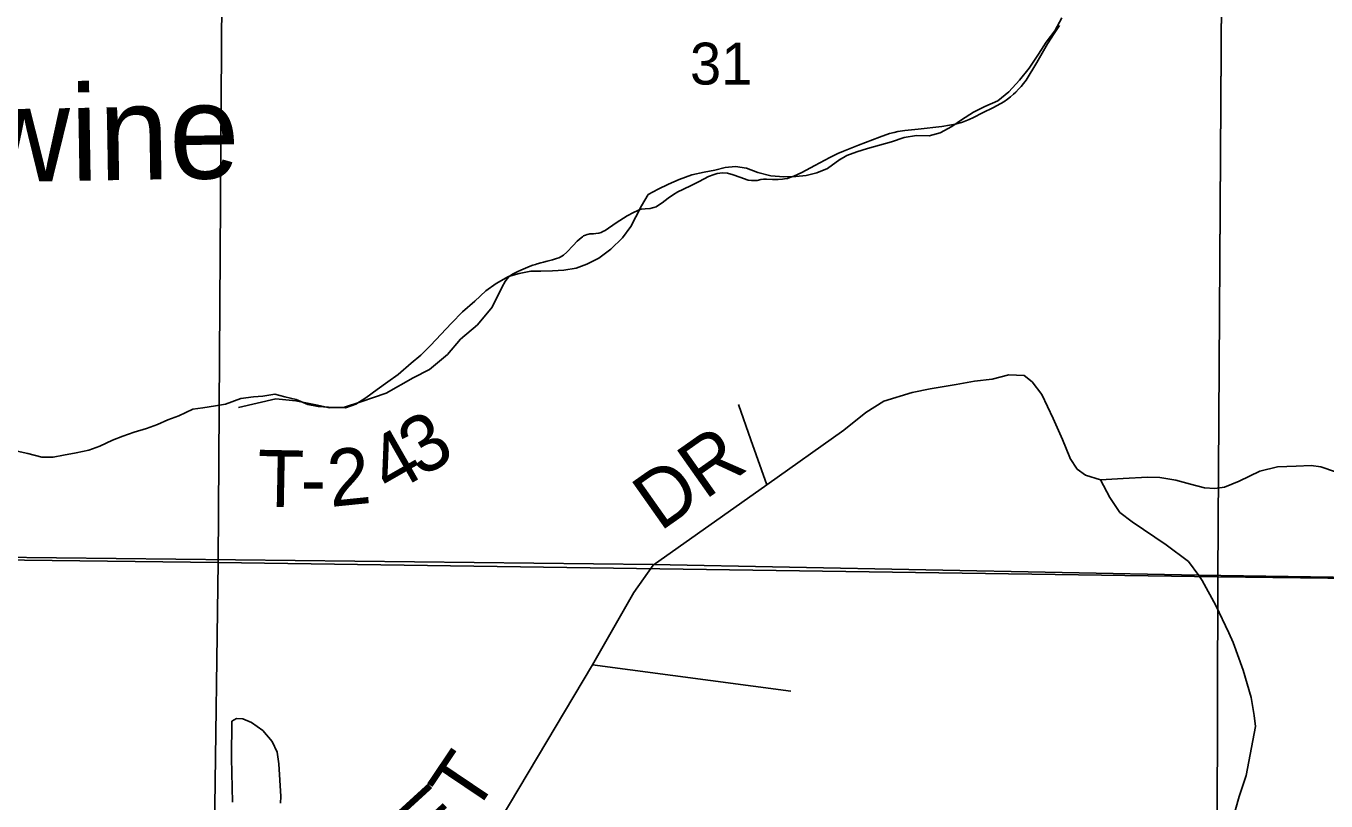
# Model space of a CAD drawing. Extents: x 0 to 34, y 0 to 22.
# Drawn here: x 6.268 to 7.567, y 18.884 to 19.658 of the extents above; entities that cross this region are included whole.
import ezdxf

# ---------------------------------------------------------------- set-up
doc = ezdxf.new("R2010")
doc.units = 0
for name, color, linetype in [('Default', 7, 'Continuous'), ('GM_X_County_Road', 7, 'Continuous'), ('GM_X_County_Road_Text', 7, 'Continuous'), ('GM_X_Minor_River', 7, 'Continuous'), ('GM_X_Minor_River_Text', 7, 'Continuous'), ('GM_X_Section', 7, 'Continuous'), ('GM_X_Section_Text', 7, 'Continuous'), ('GM_X_Township_Road', 7, 'Continuous'), ('GM_X_Township_Road_Text', 7, 'Continuous')]:
    doc.layers.add(name, color=color, linetype=linetype)

msp = doc.modelspace()

# ---------------------------------------------------------------- linework, layer by layer
at = {"layer": 'Default'}
for p, q in [((6.8944, 19.1204), (5.4005, 19.1369)), ((5.4005, 19.1369), (6.8944, 19.1204)), ((7.4393, 19.1097), (6.8944, 19.1204)), ((6.8944, 19.1204), (7.4393, 19.1097)), ((7.7845, 19.1045), (7.4393, 19.1097)), ((7.4393, 19.1097), (7.7845, 19.1045))]:
    msp.add_line(p, q, dxfattribs=at)
at = {"layer": 'GM_X_County_Road'}
for p, q in [((7.1711, 19.2958), (7.1971, 19.3001)), ((7.1971, 19.3001), (7.2154, 19.3036)), ((7.2154, 19.3036), (7.2333, 19.3055)), ((7.2333, 19.3055), (7.25, 19.3098)), ((7.25, 19.3098), (7.2652, 19.309)), ((7.2652, 19.309), (7.273, 19.3028)), ((7.273, 19.3028), (7.2827, 19.29)), ((7.1248, 19.2834), (7.1532, 19.2923)), ((7.1532, 19.2923), (7.1711, 19.2958)), ((7.2827, 19.29), (7.2943, 19.2663)), ((7.1069, 19.2721), (7.1248, 19.2834)), ((7.0851, 19.2546), (7.1069, 19.2721)), ((7.2943, 19.2663), (7.3033, 19.2453)), ((7.0081, 19.1998), (7.0851, 19.2546)), ((7.3033, 19.2453), (7.3107, 19.2272)), ((7.3107, 19.2272), (7.3111, 19.2262)), ((7.3111, 19.2262), (7.3181, 19.2157)), ((7.3181, 19.2157), (7.3265, 19.2094)), ((7.3265, 19.2094), (7.3414, 19.2048)), ((7.4798, 19.2037), (7.5006, 19.2136)), ((7.5006, 19.2136), (7.5183, 19.2179)), ((7.5183, 19.2179), (7.5368, 19.2186)), ((7.5368, 19.2186), (7.5518, 19.2192)), ((7.5518, 19.2192), (7.5615, 19.2179)), ((7.5615, 19.2179), (7.5761, 19.213)), ((6.8946, 19.1198), (7.0081, 19.1998)), ((7.3414, 19.2048), (7.364, 19.2062)), ((7.364, 19.2062), (7.3883, 19.2077)), ((7.3883, 19.2077), (7.4007, 19.2072)), ((7.4007, 19.2072), (7.4166, 19.2044)), ((7.4166, 19.2044), (7.4312, 19.2005)), ((7.4312, 19.2005), (7.4452, 19.1969)), ((7.4452, 19.1969), (7.4557, 19.1963)), ((7.4557, 19.1963), (7.4653, 19.1976)), ((7.4653, 19.1976), (7.4798, 19.2037)), ((6.8751, 19.0924), (6.8946, 19.1198)), ((6.8418, 19.0341), (6.8751, 19.0924)), ((6.8338, 19.0202), (6.8418, 19.0341)), ((6.7604, 18.8964), (6.8338, 19.0202)), ((6.7417, 18.8653), (6.7604, 18.8964))]:
    msp.add_line(p, q, dxfattribs=at)
at = {"layer": 'GM_X_Minor_River'}
for p, q in [((7.3029, 19.6663), (7.2957, 19.6535)), ((7.2957, 19.6535), (7.2872, 19.6423)), ((7.2872, 19.6423), (7.2796, 19.6303)), ((7.2796, 19.6303), (7.2701, 19.6163)), ((7.2701, 19.6163), (7.2605, 19.6043)), ((7.2605, 19.6043), (7.2498, 19.5926)), ((7.2498, 19.5926), (7.2387, 19.5835)), ((7.2147, 19.5722), (7.2027, 19.5647)), ((7.2259, 19.5779), (7.2147, 19.5722)), ((7.2387, 19.5835), (7.2259, 19.5779)), ((7.2027, 19.5647), (7.193, 19.558)), ((7.1454, 19.5468), (7.1326, 19.5426)), ((7.1575, 19.549), (7.1454, 19.5468)), ((7.1701, 19.5486), (7.1575, 19.549)), ((7.1814, 19.5516), (7.1701, 19.5486)), ((7.193, 19.558), (7.1814, 19.5516)), ((7.1085, 19.5359), (7.0979, 19.5326)), ((7.1326, 19.5426), (7.1085, 19.5359)), ((7.0811, 19.525), (7.0686, 19.5158)), ((7.0881, 19.5289), (7.0806, 19.5246)), ((7.0979, 19.5326), (7.0881, 19.5289)), ((6.933, 19.5096), (6.9206, 19.5051)), ((6.9455, 19.5123), (6.933, 19.5096)), ((6.9561, 19.5142), (6.9455, 19.5123)), ((6.9663, 19.5168), (6.9561, 19.5142)), ((6.9769, 19.5179), (6.9663, 19.5168)), ((6.9876, 19.5163), (6.9769, 19.5179)), ((6.9991, 19.5121), (6.9876, 19.5163)), ((7.0121, 19.5087), (6.9991, 19.5121)), ((7.0251, 19.5076), (7.0121, 19.5087)), ((7.0369, 19.508), (7.0251, 19.5076)), ((7.0475, 19.509), (7.0369, 19.508)), ((7.058, 19.5117), (7.0475, 19.509)), ((7.0686, 19.5158), (7.058, 19.5117)), ((6.8996, 19.4953), (6.8895, 19.49)), ((6.9097, 19.5002), (6.8996, 19.4953)), ((6.9206, 19.5051), (6.9097, 19.5002)), ((6.8895, 19.49), (6.8827, 19.4788)), ((6.8827, 19.4788), (6.8773, 19.4676)), ((6.8723, 19.4579), (6.8639, 19.4466)), ((6.8773, 19.4676), (6.8723, 19.4579)), ((6.8639, 19.4466), (6.8521, 19.4352)), ((6.8521, 19.4352), (6.8402, 19.4265)), ((6.8282, 19.4204), (6.8177, 19.4163)), ((6.8402, 19.4265), (6.8282, 19.4204)), ((6.7499, 19.4081), (6.7376, 19.4012)), ((6.7608, 19.4111), (6.7499, 19.4081)), ((6.7722, 19.4133), (6.7608, 19.4111)), ((6.7824, 19.4133), (6.7722, 19.4133)), ((6.7938, 19.4136), (6.7824, 19.4133)), ((6.8052, 19.4144), (6.7938, 19.4136)), ((6.8177, 19.4163), (6.8052, 19.4144)), ((6.7272, 19.3937), (6.7165, 19.3835)), ((6.7376, 19.4012), (6.7272, 19.3937)), ((6.7165, 19.3835), (6.7042, 19.3728)), ((6.7042, 19.3728), (6.6932, 19.3614)), ((6.6932, 19.3614), (6.6722, 19.3391)), ((6.6722, 19.3391), (6.6623, 19.3293)), ((6.6623, 19.3293), (6.6526, 19.3214)), ((6.6526, 19.3214), (6.6397, 19.31)), ((6.6296, 19.3028), (6.6189, 19.2952)), ((6.6397, 19.31), (6.6296, 19.3028)), ((6.4951, 19.2879), (6.4826, 19.286)), ((6.5046, 19.2886), (6.4951, 19.2879)), ((6.5167, 19.2905), (6.5046, 19.2886)), ((6.5267, 19.2878), (6.5167, 19.2905)), ((6.5378, 19.2851), (6.5267, 19.2878)), ((6.6073, 19.2869), (6.5976, 19.2805)), ((6.6189, 19.2952), (6.6073, 19.2869)), ((6.4347, 19.2754), (6.4208, 19.2689)), ((6.4445, 19.2768), (6.4347, 19.2754)), ((6.4574, 19.2788), (6.4445, 19.2768)), ((6.4672, 19.2806), (6.4574, 19.2788)), ((6.4826, 19.286), (6.4672, 19.2806)), ((6.5494, 19.2801), (6.5378, 19.2851)), ((6.5597, 19.2782), (6.5494, 19.2801)), ((6.57, 19.2774), (6.5597, 19.2782)), ((6.5871, 19.2767), (6.57, 19.2774)), ((6.5976, 19.2805), (6.5871, 19.2767)), ((6.4096, 19.2647), (6.3994, 19.2602)), ((6.4208, 19.2689), (6.4096, 19.2647)), ((6.3648, 19.2485), (6.3543, 19.2444)), ((6.3761, 19.2526), (6.3648, 19.2485)), ((6.3882, 19.2561), (6.3761, 19.2526)), ((6.3994, 19.2602), (6.3882, 19.2561)), ((6.3416, 19.2386), (6.3307, 19.2345)), ((6.3543, 19.2444), (6.3416, 19.2386)), ((6.2699, 19.2311), (6.2592, 19.2334)), ((6.2837, 19.2277), (6.2699, 19.2311)), ((6.2951, 19.2277), (6.2837, 19.2277)), ((6.3053, 19.2295), (6.2951, 19.2277)), ((6.3182, 19.2318), (6.3053, 19.2295)), ((6.3307, 19.2345), (6.3182, 19.2318))]:
    msp.add_line(p, q, dxfattribs=at)
at = {"layer": 'GM_X_Section'}
for p, q in [((6.4665, 20.1167), (6.4599, 19.1223)), ((6.4599, 19.1223), (6.4665, 20.1167)), ((7.4653, 20.105), (7.4585, 19.1081)), ((7.4585, 19.1081), (7.4653, 20.105)), ((6.4599, 19.1223), (5.5458, 19.1336)), ((5.5458, 19.1336), (6.4599, 19.1223)), ((6.4599, 19.1223), (6.4465, 18.0895)), ((6.4465, 18.0895), (6.4599, 19.1223)), ((7.4585, 19.1081), (6.4599, 19.1223)), ((6.4599, 19.1223), (7.4585, 19.1081)), ((7.4585, 19.1081), (7.457, 18.0478)), ((8.4398, 19.0954), (7.4585, 19.1081))]:
    msp.add_line(p, q, dxfattribs=at)
at = {"layer": 'GM_X_Township_Road'}
for p, q in [((7.2886, 19.6404), (7.295, 19.6508)), ((7.295, 19.6508), (7.3004, 19.6588)), ((7.2778, 19.622), (7.2886, 19.6404)), ((7.267, 19.6042), (7.2778, 19.622)), ((7.2622, 19.598), (7.2645, 19.6007)), ((7.2645, 19.6007), (7.267, 19.6042)), ((7.2485, 19.5851), (7.2514, 19.5874)), ((7.2514, 19.5874), (7.2546, 19.5901)), ((7.2546, 19.5901), (7.2569, 19.5923)), ((7.2569, 19.5923), (7.2596, 19.5951)), ((7.2596, 19.5951), (7.2622, 19.598)), ((7.2235, 19.5715), (7.2345, 19.577)), ((7.2345, 19.577), (7.2447, 19.5825)), ((7.2447, 19.5825), (7.2485, 19.5851)), ((7.1828, 19.558), (7.1907, 19.5593)), ((7.1907, 19.5593), (7.1947, 19.56)), ((7.1947, 19.56), (7.1975, 19.5606)), ((7.1975, 19.5606), (7.2012, 19.5616)), ((7.2012, 19.5616), (7.2027, 19.562)), ((7.2027, 19.562), (7.2034, 19.5623)), ((7.2034, 19.5623), (7.2103, 19.565)), ((7.2103, 19.565), (7.2145, 19.5669)), ((7.2145, 19.5669), (7.2235, 19.5715)), ((7.0998, 19.5391), (7.1207, 19.5473)), ((7.1207, 19.5473), (7.1306, 19.5508)), ((7.1306, 19.5508), (7.1352, 19.552)), ((7.1352, 19.552), (7.1391, 19.5528)), ((7.1391, 19.5528), (7.1458, 19.5538)), ((7.1458, 19.5538), (7.1593, 19.5552)), ((7.1593, 19.5552), (7.1828, 19.558)), ((7.0789, 19.5308), (7.0848, 19.5333)), ((7.0848, 19.5333), (7.0998, 19.5391)), ((7.056, 19.5188), (7.071, 19.5268)), ((7.071, 19.5268), (7.0789, 19.5308)), ((6.9405, 19.5029), (6.9498, 19.5078)), ((6.9498, 19.5078), (6.9554, 19.51)), ((6.9554, 19.51), (6.9585, 19.5109)), ((6.9585, 19.5109), (6.961, 19.5113)), ((6.961, 19.5113), (6.9642, 19.5115)), ((6.9642, 19.5115), (6.9687, 19.5113)), ((6.9687, 19.5113), (6.9745, 19.5097)), ((6.9745, 19.5097), (6.981, 19.5074)), ((6.981, 19.5074), (6.9893, 19.5044)), ((7.031, 19.5068), (7.035, 19.5082)), ((7.035, 19.5082), (7.0429, 19.5118)), ((7.0429, 19.5118), (7.056, 19.5188)), ((6.9193, 19.4926), (6.9243, 19.4951)), ((6.9243, 19.4951), (6.9333, 19.4992)), ((6.9333, 19.4992), (6.9405, 19.5029)), ((6.9893, 19.5044), (6.9927, 19.5038)), ((6.9927, 19.5038), (6.9953, 19.5038)), ((6.9953, 19.5038), (6.9984, 19.5041)), ((6.9984, 19.5041), (7.002, 19.5049)), ((7.002, 19.5049), (7.0046, 19.5053)), ((7.0046, 19.5053), (7.0076, 19.5053)), ((7.0076, 19.5053), (7.0137, 19.505)), ((7.0137, 19.505), (7.0193, 19.505)), ((7.0193, 19.505), (7.0237, 19.5053)), ((7.0237, 19.5053), (7.0256, 19.5055)), ((7.0256, 19.5055), (7.0286, 19.5061)), ((7.0286, 19.5061), (7.031, 19.5068)), ((6.899, 19.4785), (6.9036, 19.4817)), ((6.9036, 19.4817), (6.9095, 19.4862)), ((6.9095, 19.4862), (6.915, 19.4901)), ((6.915, 19.4901), (6.9193, 19.4926)), ((6.8577, 19.4617), (6.8684, 19.4685)), ((6.8684, 19.4685), (6.8749, 19.472)), ((6.8749, 19.472), (6.8786, 19.4738)), ((6.8786, 19.4738), (6.8807, 19.4747)), ((6.8807, 19.4747), (6.8826, 19.4752)), ((6.8826, 19.4752), (6.8864, 19.4757)), ((6.8864, 19.4757), (6.8914, 19.4761)), ((6.8914, 19.4761), (6.8938, 19.4765)), ((6.8938, 19.4765), (6.8951, 19.4769)), ((6.8951, 19.4769), (6.8974, 19.4778)), ((6.8974, 19.4778), (6.899, 19.4785)), ((6.8464, 19.4541), (6.8577, 19.4617)), ((6.8145, 19.4391), (6.8186, 19.4432)), ((6.8186, 19.4432), (6.8226, 19.4467)), ((6.8226, 19.4467), (6.824, 19.4478)), ((6.824, 19.4478), (6.825, 19.4485)), ((6.825, 19.4485), (6.8269, 19.4494)), ((6.8269, 19.4494), (6.8285, 19.45)), ((6.8285, 19.45), (6.8303, 19.4504)), ((6.8303, 19.4504), (6.8313, 19.4505)), ((6.8313, 19.4505), (6.8327, 19.4506)), ((6.8327, 19.4506), (6.835, 19.4506)), ((6.835, 19.4506), (6.8374, 19.4509)), ((6.8374, 19.4509), (6.8401, 19.4514)), ((6.8401, 19.4514), (6.8427, 19.4521)), ((6.8427, 19.4521), (6.8444, 19.4529)), ((6.8444, 19.4529), (6.8464, 19.4541)), ((6.8032, 19.4282), (6.8049, 19.4295)), ((6.8049, 19.4295), (6.8084, 19.4322)), ((6.8084, 19.4322), (6.8145, 19.4391)), ((6.7622, 19.4144), (6.767, 19.4165)), ((6.767, 19.4165), (6.7718, 19.4184)), ((6.7718, 19.4184), (6.7744, 19.4193)), ((6.7744, 19.4193), (6.7769, 19.4201)), ((6.7769, 19.4201), (6.7785, 19.4206)), ((6.7785, 19.4206), (6.7822, 19.4216)), ((6.7822, 19.4216), (6.785, 19.4225)), ((6.785, 19.4225), (6.7887, 19.4234)), ((6.7887, 19.4234), (6.7938, 19.4247)), ((6.7938, 19.4247), (6.798, 19.426)), ((6.798, 19.426), (6.8003, 19.4268)), ((6.8003, 19.4268), (6.8017, 19.4274)), ((6.8017, 19.4274), (6.8032, 19.4282)), ((6.7468, 19.4032), (6.7484, 19.4055)), ((6.7484, 19.4055), (6.7508, 19.408)), ((6.7508, 19.408), (6.7541, 19.4103)), ((6.7541, 19.4103), (6.7561, 19.4114)), ((6.7561, 19.4114), (6.7592, 19.413)), ((6.7592, 19.413), (6.7622, 19.4144)), ((6.7338, 19.3774), (6.7436, 19.3976)), ((6.7436, 19.3976), (6.7468, 19.4032)), ((6.7189, 19.3597), (6.7338, 19.3774)), ((6.7019, 19.3453), (6.7189, 19.3597)), ((6.6892, 19.3302), (6.7019, 19.3453)), ((6.671, 19.3152), (6.6892, 19.3302)), ((6.6549, 19.3067), (6.671, 19.3152)), ((6.6279, 19.2916), (6.6549, 19.3067)), ((6.6025, 19.2827), (6.6279, 19.2916)), ((6.4801, 19.2772), (6.5177, 19.2857)), ((6.5177, 19.2857), (6.5376, 19.2839)), ((6.5376, 19.2839), (6.5575, 19.2799)), ((6.5575, 19.2799), (6.5713, 19.2768)), ((6.5713, 19.2768), (6.586, 19.2776)), ((6.586, 19.2776), (6.6025, 19.2827)), ((6.9922, 19.2449), (6.9799, 19.28)), ((7.0081, 19.1998), (6.9922, 19.2449)), ((7.3506, 19.1874), (7.3414, 19.2048)), ((7.3607, 19.1723), (7.3506, 19.1874)), ((7.3729, 19.1629), (7.3607, 19.1723)), ((7.4069, 19.1398), (7.3729, 19.1629)), ((7.4293, 19.1232), (7.4069, 19.1398)), ((7.4395, 19.1092), (7.4293, 19.1232)), ((7.443, 19.1044), (7.4395, 19.1092)), ((7.4567, 19.0792), (7.443, 19.1044)), ((7.4695, 19.052), (7.4567, 19.0792)), ((7.474, 19.0423), (7.4695, 19.052)), ((7.4841, 19.0149), (7.474, 19.0423)), ((6.8338, 19.0202), (7.0321, 18.9937)), ((7.4921, 18.9875), (7.4841, 19.0149)), ((7.4949, 18.9694), (7.4921, 18.9875)), ((6.4734, 18.9267), (6.4737, 18.9638)), ((6.4784, 18.9664), (6.4737, 18.9638)), ((6.4845, 18.9662), (6.4784, 18.9664)), ((6.4933, 18.9624), (6.4845, 18.9662)), ((6.5044, 18.9545), (6.4933, 18.9624)), ((7.4964, 18.9586), (7.4949, 18.9694)), ((6.5138, 18.9436), (6.5044, 18.9545)), ((7.487, 18.9095), (7.4964, 18.9586)), ((6.519, 18.9328), (6.5138, 18.9436)), ((6.4744, 18.8827), (6.4734, 18.9267)), ((6.5205, 18.921), (6.519, 18.9328)), ((6.5225, 18.8884), (6.5205, 18.921)), ((7.4798, 18.8886), (7.487, 18.9095)), ((6.5221, 18.8817), (6.5225, 18.8884)), ((7.4733, 18.8648), (7.4798, 18.8886))]:
    msp.add_line(p, q, dxfattribs=at)

# ---------------------------------------------------------------- texts
at = {"layer": 'GM_X_County_Road_Text'}
for s, height, rotation, p in [('DR', 0.05682, 35.1941, (6.9013, 19.1526)), ('T', 0.0568, 56.0446, (6.7149, 18.8684)), ('E', 0.0568, 42.3949, (6.6739, 18.8286))]:
    msp.add_text(s, height=height, rotation=rotation, dxfattribs=at).set_placement(p)
at = {"layer": 'GM_X_Minor_River_Text'}
msp.add_text('Brandywine', height=0.09471, rotation=0.9622, dxfattribs=at).set_placement((5.8203, 19.4953))
at = {"layer": 'GM_X_Section_Text'}
msp.add_text('31', height=0.04186, rotation=0, dxfattribs=at).set_placement((6.9313, 19.5998))
at = {"layer": 'GM_X_Township_Road_Text'}
for s, rotation, p in [('3', 30.314, (6.6623, 19.2067)), ('4', 29.6742, (6.6313, 19.1891)), ('T', 358.8857, (6.4988, 19.1782)), ('2', 5.8481, (6.5722, 19.1777)), ('-', 359.9076, (6.5424, 19.1774))]:
    msp.add_text(s, height=0.0568, rotation=rotation, dxfattribs=at).set_placement(p)

doc.saveas('drawing.dxf')
